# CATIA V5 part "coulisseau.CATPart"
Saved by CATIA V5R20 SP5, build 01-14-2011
Part number: coulisseau
Publications: "Droite.2"
Bounding box of the stored display mesh (mm): x -125 to 0, y 1387.331 to 1656.458, z 518.273 to 761.144
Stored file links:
  F:\iao fini\coulisseau.CATPart
  F:\iao fini\iao-finipbgliss.CATProduct
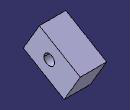
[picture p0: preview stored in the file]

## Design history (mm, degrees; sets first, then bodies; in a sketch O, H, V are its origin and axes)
External parameters (linked from other documents)
  External.epaisseur = 125 mm
  `External.longueur bati` = 1 mm
  External.rayontrou = 50 mm
Set1
  Plane1 "Plancouli": linked copy from another document
  Plane2 "plan coulisseau": linked copy from another document
  Point1: linked copy from another document
  Line1: linked copy from another document
  Plane3 "Plan profil cou": linked copy from another document
  Plane4 "plan profil": linked copy from another document
  Plane5 "Plancouli": linked copy from another document
Body1 (main body)
  Sketch1 on Plane5, origin (0, 666.3122, 1154.012), H (-1, 0, 0), V (0, -0.8619, 0.5071)
    point P1 (0, -886.2187)
    line L1 (0, -886.2187) -> (125, -886.2187)
    line L2 (125, -886.2187) -> (125, -1110.2187)
    line L3 (125, -1110.2187) -> (0, -1110.2187)
    line L4 (0, -1110.2187) -> (0, -886.2187)
    reference projected line E1 (0, -2478.346) -> (0, 709.5469) from Line1
    reference projected line E2 (0, -2478.346) -> (0, 709.5469) from Line1
    distance L2 E2 = 125 {= External.epaisseur}
    distance L3 L1 = 224 {= 224*`External.longueur bati`}
    coincidence: P1 V
    horizontal: L1 H, L3 H
    vertical: L2 V, L4 V
    parallelism: E1 L2
    perpendicularity: L3 L4, L1 L4
  Sketch2 on Plane3, origin (0, 0, 0), H (0, 1, 0), V (0, 0, 1)
    circle A1 centre (1510.0387, 645.4906) radius 25
    point P1 (1510.0387, 645.4906)
    reference projected point E1 (1510.0387, 645.4906) from Point1
    radius A1 = 25 {= External.rayontrou *1/2}
    coincidence: E1 P1
  Pad1: profile Sketch1, direction (0, 0.5071, 0.8619), length 65.574 {= `External.longueur bati` *75-9.426mm}, opposite side length 84.426 {= `External.longueur bati` *75+9.426mm}
  Pocket1: profile Sketch2, direction (-1, 0, 0), length 125 {= External.epaisseur}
